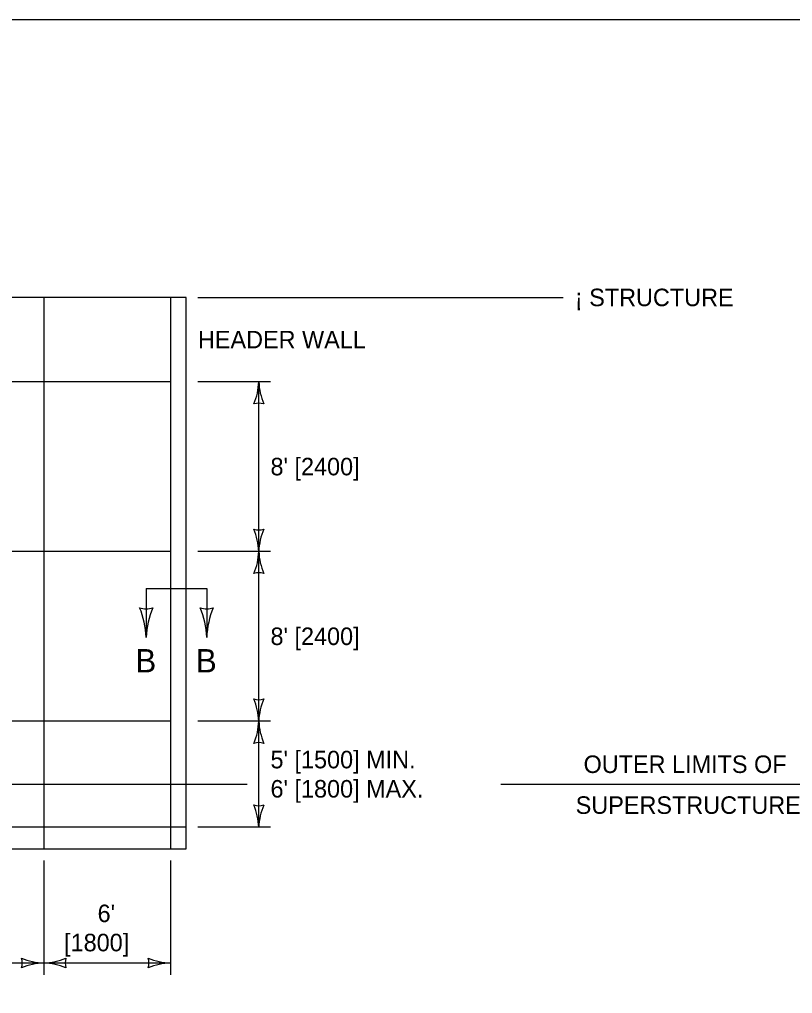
# Model space of a CAD drawing. Extents: x 49991.4 to 50021, y 49987.6 to 50011.4.
# Drawn here: x 50003.843 to 50006.491, y 49995.663 to 49998.999 of the extents above; entities that cross this region are included whole.
import ezdxf

# ---------------------------------------------------------------- set-up
doc = ezdxf.new("R2010")
doc.units = 0
for name, color, linetype in [('Level 1', 7, 'Continuous'), ('Level 2', 7, 'Continuous'), ('Level 3', 7, 'Continuous'), ('Level 5', 7, 'Continuous'), ('Level 6', 7, 'Continuous')]:
    doc.layers.add(name, color=color, linetype=linetype)

msp = doc.modelspace()

# ---------------------------------------------------------------- linework, layer by layer
at = {"layer": 'Level 1'}
for p, q in [((50004.4142, 49998.0473), (50001.7265, 49998.0473)), ((50003.9259, 49998.0473), (50003.9259, 49996.1588)), ((50004.3599, 49998.0473), (50004.3599, 49996.1588)), ((50004.4142, 49996.1588), (50004.4142, 49998.0473)), ((50004.3599, 49997.7584), (50001.7265, 49997.7584)), ((50004.3599, 49997.1775), (50001.7265, 49997.1775)), ((50004.3599, 49996.596), (50001.7296, 49996.596)), ((50004.4142, 49996.2328), (50001.7265, 49996.2328)), ((50001.7265, 49996.1588), (50004.4142, 49996.1588))]:
    msp.add_line(p, q, dxfattribs=at)
msp.add_lwpolyline([(49999.3835, 49998.9992), (50016.7501, 49998.9992), (50016.7501, 49987.7988), (49999.3835, 49987.7988)], close=True, dxfattribs=at)
at = {"layer": 'Level 3'}
for p, q in [((50004.7027, 49997.7584), (50004.4542, 49997.7584)), ((50004.6627, 49997.1775), (50004.6627, 49997.7584)), ((50004.7027, 49997.1775), (50004.4542, 49997.1775)), ((50004.6627, 49996.596), (50004.6627, 49997.1775)), ((50004.7027, 49996.596), (50004.4542, 49996.596)), ((50004.6627, 49996.2328), (50004.6627, 49996.596)), ((50004.7027, 49996.2328), (50004.4542, 49996.2328)), ((50003.9259, 49996.1188), (50003.9259, 49995.7277)), ((50004.3599, 49996.1188), (50004.3599, 49995.7277)), ((50003.4902, 49995.7677), (50003.9259, 49995.7677)), ((50003.9259, 49995.7677), (50004.3599, 49995.7677))]:
    msp.add_line(p, q, dxfattribs=at)
for centre, radius, start, end in [((50004.4406, 49997.7676), 0.2223, 337.456, 357.6395), ((50004.8954, 49997.7699), 0.233, 182.8273, 202.0772), ((50004.6627, 49997.6302), 0.0548, 72.1388, 107.8612), ((50004.6627, 49997.3057), 0.0548, 252.1388, 287.8612), ((50004.43, 49997.166), 0.233, 2.8273, 22.0772), ((50004.8848, 49997.1683), 0.2223, 157.456, 177.6395), ((50004.4406, 49997.1867), 0.2223, 337.456, 357.6395), ((50004.8954, 49997.189), 0.233, 182.8273, 202.0772), ((50004.6627, 49997.0493), 0.0548, 72.1388, 107.8612), ((50004.2769, 49997.054), 0.073, 252.1388, 287.8612), ((50003.9666, 49996.8677), 0.3107, 2.8273, 22.0772), ((50004.5731, 49996.8708), 0.2964, 157.456, 177.6395), ((50004.4842, 49997.054), 0.073, 252.1388, 287.8612), ((50004.1739, 49996.8677), 0.3107, 2.8273, 22.0772), ((50004.7804, 49996.8708), 0.2964, 157.456, 177.6395), ((50004.6627, 49996.7242), 0.0548, 252.1388, 287.8612), ((50004.43, 49996.5845), 0.233, 2.8273, 22.0772), ((50004.8848, 49996.5868), 0.2223, 157.456, 177.6395), ((50004.4406, 49996.6052), 0.2223, 337.456, 357.6395), ((50004.8954, 49996.6075), 0.233, 182.8273, 202.0772), ((50004.6627, 49996.4678), 0.0548, 72.1388, 107.8612), ((50004.6627, 49996.361), 0.0548, 252.1388, 287.8612), ((50004.43, 49996.2213), 0.233, 2.8273, 22.0772), ((50004.8848, 49996.2236), 0.2223, 157.456, 177.6395), ((50003.9351, 49995.9898), 0.2223, 247.456, 267.6395), ((50003.7977, 49995.7677), 0.0548, 342.1388, 17.8612), ((50003.9144, 49996.0004), 0.233, 272.8273, 292.0772), ((50004.0541, 49995.7677), 0.0548, 162.1388, 197.8612), ((50004.3691, 49995.9898), 0.2223, 247.456, 267.6395), ((50004.2317, 49995.7677), 0.0548, 342.1388, 17.8612), ((50003.9374, 49995.535), 0.233, 92.8273, 112.0772), ((50003.9167, 49995.5456), 0.2223, 67.456, 87.6395), ((50004.3714, 49995.535), 0.233, 92.8273, 112.0772)]:
    msp.add_arc(centre, radius, start, end, dxfattribs=at)
at = {"layer": 'Level 5'}
for p, q in [((50004.4542, 49998.0473), (50005.7054, 49998.0473)), ((50004.6227, 49996.3785), (50000.3371, 49996.3785)), ((50006.5603, 49996.3785), (50005.4916, 49996.3785))]:
    msp.add_line(p, q, dxfattribs=at)
at = {"layer": 'Level 6'}
for p, q in [((50004.2769, 49997.0505), (50004.2769, 49996.883)), ((50004.2769, 49997.0505), (50004.4842, 49997.0505)), ((50004.4842, 49997.0505), (50004.4842, 49996.883))]:
    msp.add_line(p, q, dxfattribs=at)

# ---------------------------------------------------------------- texts
at = {"layer": 'Level 2'}
for s, height, p in [('¡ STRUCTURE', 0.06, (50005.7454, 49998.0173)), ('HEADER WALL', 0.06, (50004.4542, 49997.8728)), ("8' [2400]", 0.06, (50004.7027, 49997.4379)), ("8' [2400]", 0.06, (50004.7027, 49996.8567)), ('B', 0.08, (50004.2399, 49996.763)), ('B', 0.08, (50004.4472, 49996.763)), ("5' [1500] MIN.", 0.06, (50004.7027, 49996.4344)), ('OUTER LIMITS OF', 0.06, (50005.7752, 49996.4185)), ("6' [1800] MAX.", 0.06, (50004.7027, 49996.3344)), ('SUPERSTRUCTURE', 0.06, (50005.7482, 49996.2785)), ("6'", 0.06, (50004.1104, 49995.9077)), ('[1800]', 0.06, (50003.9957, 49995.8077))]:
    msp.add_text(s, height=height, dxfattribs=at).set_placement(p)

doc.saveas('drawing.dxf')
